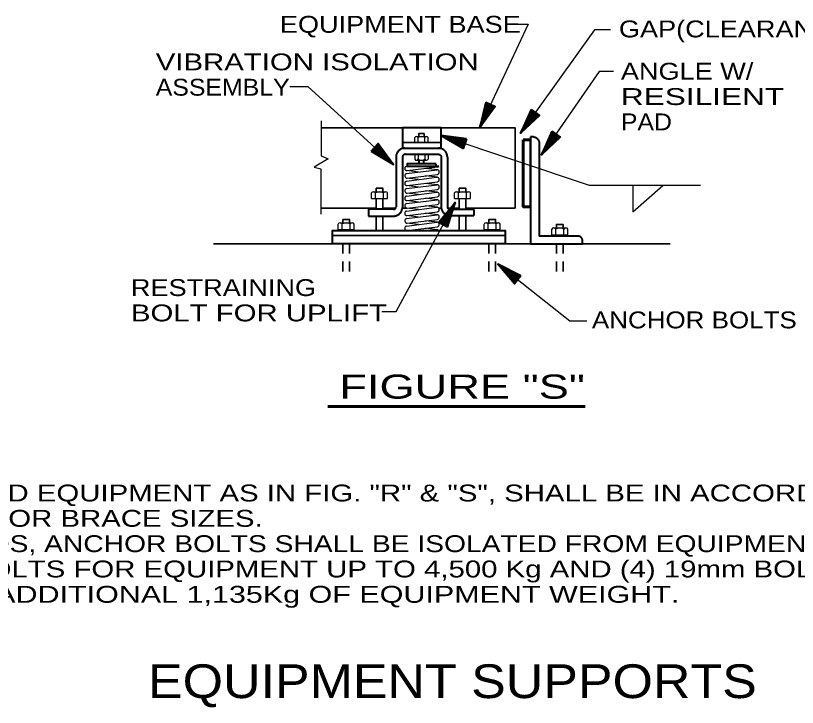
# Model space of a CAD drawing. Extents: x 55 to 190, y 198 to 264.
# Drawn here: x 114.38 to 126.14, y 231.1 to 241.51 of the extents above; entities that cross this region are included whole.
import ezdxf
from ezdxf.enums import TextEntityAlignment as Align

# ---------------------------------------------------------------- set-up
doc = ezdxf.new("R2010")
doc.units = 0
doc.header["$LTSCALE"] = 0.1
doc.linetypes.add('SHORT_DASHED', pattern=[2.7, 1.5, -1.2])
doc.layers.add('2', color=7, linetype='Continuous', lineweight=40)

msp = doc.modelspace()

# ---------------------------------------------------------------- linework, layer by layer
at = {"layer": '2'}
for p, q in [((121.3624, 239.8256), (121.473, 240.196)), ((121.3624, 239.8256), (121.4926, 240.1876)), ((121.3624, 239.8256), (121.5079, 240.1796)), ((121.5241, 240.1725), (121.3624, 239.8256)), ((121.3624, 239.8256), (121.5413, 240.164)), ((121.3624, 239.8256), (121.5752, 240.1481)), ((121.9762, 239.7399), (122.1527, 240.0838)), ((121.9762, 239.7399), (122.1705, 240.0719)), ((121.9762, 239.7399), (122.184, 240.0616)), ((122.1985, 240.0513), (121.9762, 239.7399)), ((121.9762, 239.7399), (122.2139, 240.0399)), ((121.9762, 239.7399), (122.2443, 240.0182)), ((121.1399, 239.5832), (120.7766, 239.7039)), ((120.7766, 239.7039), (121.151, 239.6161)), ((120.7766, 239.7039), (121.1217, 239.5298)), ((120.7766, 239.7039), (121.1336, 239.565)), ((120.7766, 239.7039), (121.1452, 239.6002)), ((120.7766, 239.7039), (121.1574, 239.6367)), ((122.1744, 239.6856), (122.1279, 239.6856)), ((122.2903, 239.4115), (122.4615, 239.7581)), ((122.2903, 239.4115), (122.4795, 239.7465)), ((122.2903, 239.4115), (122.493, 239.7362)), ((122.5078, 239.7264), (122.2903, 239.4115)), ((122.2903, 239.4115), (122.5234, 239.7153)), ((122.2903, 239.4115), (122.5541, 239.6939)), ((120.0633, 239.2687), (119.8183, 239.5676)), ((122.1279, 238.6326), (122.1279, 239.6377)), ((122.2591, 239.5944), (122.2591, 238.1915)), ((120.0633, 239.2687), (119.7424, 239.4843)), ((120.0633, 239.2687), (119.7564, 239.5004)), ((120.0633, 239.2687), (119.7683, 239.5126)), ((119.78, 239.5261), (120.0633, 239.2687)), ((120.0633, 239.2687), (119.7932, 239.5399)), ((120.1035, 239.3792), (120.1035, 238.63)), ((120.2014, 239.3816), (120.2014, 238.6228)), ((120.2438, 239.4216), (120.742, 239.4216)), ((120.4464, 239.3324), (120.4464, 239.2755)), ((120.5237, 239.2755), (120.5237, 239.3324)), ((120.783, 239.3792), (120.783, 238.6305)), ((120.8769, 239.3792), (120.8769, 238.6305)), ((120.2623, 239.2443), (120.7478, 239.2443)), ((120.7044, 239.2761), (120.7044, 239.2443)), ((120.9912, 238.6977), (120.7605, 238.3876)), ((120.9912, 238.6977), (120.7933, 238.3699)), ((120.8102, 238.3606), (120.9912, 238.6977)), ((120.9912, 238.6977), (120.8259, 238.3524)), ((120.9912, 238.6977), (120.8407, 238.3439)), ((120.9912, 238.6977), (120.8597, 238.3342)), ((120.0625, 238.5956), (119.6889, 238.5956)), ((119.6889, 238.5956), (119.6889, 238.4929)), ((120.914, 238.5937), (121.2727, 238.5937)), ((121.2727, 238.5929), (121.2727, 238.5014)), ((119.6889, 238.4916), (120.057, 238.4916)), ((120.9166, 238.5001), (121.2727, 238.5001)), ((122.8417, 238.1915), (122.2591, 238.1915)), ((121.9342, 237.533), (121.6336, 237.7698)), ((121.6336, 237.7698), (121.9561, 237.5603)), ((121.6336, 237.7698), (121.899, 237.4888)), ((121.6336, 237.7698), (121.9223, 237.5182)), ((121.6336, 237.7698), (121.945, 237.5473)), ((121.6336, 237.7698), (121.9689, 237.5774))]:
    msp.add_line(p, q, dxfattribs=at)
at = {"layer": '2', "lineweight": 25}
for p, q in [((120.4107, 239.6899), (120.561, 239.6899)), ((120.3856, 239.605), (120.3856, 239.6748)), ((120.3856, 239.605), (120.5861, 239.605)), ((120.4353, 239.605), (120.4353, 239.6748)), ((120.5361, 239.605), (120.5361, 239.6748)), ((120.5861, 239.605), (120.5861, 239.6743)), ((120.3856, 239.4166), (120.5861, 239.4166)), ((120.3856, 239.4166), (120.3856, 239.3467)), ((120.4107, 239.3316), (120.561, 239.3316)), ((120.4353, 239.4166), (120.4353, 239.3467)), ((120.5361, 239.4166), (120.5361, 239.3467)), ((120.5861, 239.4166), (120.5861, 239.3472)), ((120.2692, 239.1755), (120.7269, 239.2319)), ((120.4406, 239.1536), (120.2623, 239.1753)), ((120.2626, 239.1316), (120.7205, 239.188)), ((120.2694, 239.0628), (120.7274, 239.1192)), ((120.7272, 239.188), (120.5486, 239.2099)), ((120.7277, 239.0752), (120.5488, 239.0972)), ((120.2623, 239.0189), (120.72, 239.0752)), ((120.4409, 239.0409), (120.2628, 239.0626)), ((120.2692, 238.9501), (120.7269, 239.0065)), ((120.7272, 238.9625), (120.5486, 238.9845)), ((120.4406, 238.9281), (120.2623, 238.9498)), ((120.2626, 238.9062), (120.7205, 238.9625)), ((120.2694, 238.8374), (120.7274, 238.8938)), ((120.7277, 238.8498), (120.5488, 238.8718)), ((123.6683, 238.957), (123.6683, 238.5569)), ((123.6683, 238.5569), (124.1202, 238.9538)), ((119.7342, 238.7556), (119.7342, 238.8403)), ((119.7342, 238.7556), (119.9768, 238.7556)), ((119.7646, 238.8588), (119.9466, 238.8588)), ((119.7942, 238.7556), (119.7942, 238.8403)), ((119.9162, 238.7556), (119.9162, 238.8403)), ((119.9768, 238.7556), (119.9768, 238.8398)), ((120.2623, 238.7935), (120.72, 238.8498)), ((120.4409, 238.8154), (120.2628, 238.8371)), ((120.2692, 238.7247), (120.7269, 238.781)), ((120.7272, 238.7371), (120.5486, 238.7591)), ((120.9838, 238.7556), (120.9838, 238.8403)), ((120.9838, 238.7556), (121.2264, 238.7556)), ((121.0142, 238.8588), (121.1963, 238.8588)), ((121.0439, 238.7556), (121.0439, 238.8403)), ((121.1658, 238.7556), (121.1658, 238.8403)), ((121.2264, 238.7556), (121.2264, 238.8398)), ((120.4406, 238.7027), (120.2623, 238.7244)), ((120.2626, 238.6808), (120.7205, 238.7371)), ((120.2694, 238.612), (120.7274, 238.6683)), ((120.7277, 238.6244), (120.5488, 238.6464)), ((120.2623, 238.568), (120.72, 238.6244)), ((120.2626, 238.4553), (120.7205, 238.5114)), ((120.4409, 238.59), (120.2628, 238.6117)), ((120.2692, 238.4993), (120.7269, 238.5553)), ((120.7272, 238.5114), (120.5486, 238.5334)), ((119.263, 238.3913), (119.445, 238.3913)), ((120.4406, 238.477), (120.2623, 238.499)), ((120.2623, 238.3426), (120.72, 238.3987)), ((120.2694, 238.3865), (120.7274, 238.4426)), ((120.7277, 238.3987), (120.5488, 238.4207)), ((121.4606, 238.3913), (121.6426, 238.3913)), ((119.2325, 238.2881), (119.2325, 238.3728)), ((119.2325, 238.2881), (119.4752, 238.2881)), ((119.2926, 238.2881), (119.2926, 238.3728)), ((119.4146, 238.2881), (119.4146, 238.3728)), ((119.4752, 238.2881), (119.4752, 238.3723)), ((120.4409, 238.3643), (120.2628, 238.3863)), ((120.2692, 238.2738), (120.7269, 238.3299)), ((120.7203, 238.2871), (120.5486, 238.308)), ((120.6123, 238.2738), (120.7203, 238.2871)), ((121.4302, 238.2881), (121.4302, 238.3728)), ((121.4302, 238.2881), (121.6728, 238.2881)), ((121.4902, 238.2881), (121.4902, 238.3728)), ((121.6122, 238.2881), (121.6122, 238.3728)), ((121.6728, 238.2881), (121.6728, 238.3723)), ((122.4459, 238.2117), (122.4459, 238.2963)), ((122.4763, 238.3148), (122.6583, 238.3148)), ((122.506, 238.2117), (122.506, 238.2963)), ((122.6279, 238.2117), (122.6279, 238.2963)), ((122.6885, 238.2117), (122.6885, 238.2958)), ((122.4459, 238.2117), (122.6885, 238.2117))]:
    msp.add_line(p, q, dxfattribs=at)
at = {"layer": '2', "lineweight": 35}
for p, q in [((120.202, 239.5981), (120.7835, 239.5981)), ((119.8059, 238.7556), (119.8059, 238.5948)), ((119.9056, 238.7556), (119.9056, 238.5966)), ((121.0555, 238.7556), (121.0555, 238.5948)), ((121.1552, 238.7556), (121.1552, 238.5937)), ((119.8059, 238.6109), (118.987, 238.6117)), ((120.0975, 238.6104), (119.9056, 238.6106)), ((120.2647, 238.6104), (120.1988, 238.6104)), ((120.7848, 238.6099), (120.7488, 238.6099)), ((121.0555, 238.6096), (120.883, 238.6099)), ((121.8953, 238.6088), (121.1552, 238.6096)), ((119.8059, 238.4916), (119.8059, 238.2738)), ((119.9056, 238.4916), (119.9056, 238.2738)), ((121.0555, 238.5001), (121.0555, 238.2738)), ((121.1552, 238.5001), (121.1552, 238.2738)), ((119.1479, 238.1989), (121.7471, 238.1989)), ((117.3582, 238.0762), (124.2287, 238.0762))]:
    msp.add_line(p, q, dxfattribs=at)
at = {"layer": '2', "lineweight": 60}
for p, q in [((122.1279, 239.6377), (122.0167, 239.6377)), ((119.0772, 235.6246), (122.9497, 235.6246))]:
    msp.add_line(p, q, dxfattribs=at)
at = {"layer": '2', "linetype": 'SHORT_DASHED', "lineweight": 35}
for p, q in [((119.3042, 238.0765), (119.3042, 237.569)), ((119.404, 238.0765), (119.404, 237.569)), ((121.5019, 238.0765), (121.5019, 237.569)), ((121.6016, 238.0765), (121.6016, 237.569)), ((122.5176, 238.0765), (122.5176, 237.569)), ((122.6173, 238.0765), (122.6173, 237.569))]:
    msp.add_line(p, q, dxfattribs=at)
at = {"layer": '2', "lineweight": 25}
for points in [[(121.8479, 241.3816), (122.0906, 241.3816), (121.3624, 239.8256)], [(123.3325, 241.2962), (123.0899, 241.2962), (121.9762, 239.7399)], [(123.3754, 240.6678), (123.1613, 240.6678), (122.2903, 239.4115)], [(118.507, 240.4394), (118.7782, 240.4394), (120.0633, 239.2687)], [(118.978, 239.9251), (118.978, 239.397), (119.0849, 239.3541), (118.8708, 239.2255), (118.9708, 239.2041), (118.9708, 238.5188)], [(120.7766, 239.7039), (123.0108, 238.9578), (124.6856, 238.9578)], [(119.8919, 237.0559), (120.1062, 237.0559), (120.9912, 238.6977)], [(122.9756, 236.9131), (122.7187, 236.9131), (121.6336, 237.7698)]]:
    msp.add_lwpolyline(points, dxfattribs=at)
at = {"layer": '2'}
for points in [[(121.4556, 240.2042), (121.5939, 240.1391), (121.3624, 239.8256)], [(121.4556, 240.2042), (121.3624, 239.8256), (121.5587, 240.1563)], [(122.1369, 240.0952), (122.2612, 240.006), (121.9762, 239.7399)], [(122.1369, 240.0952), (121.9762, 239.7399), (122.2295, 240.0293)], [(121.1635, 239.6552), (121.1148, 239.51), (120.7766, 239.7039)], [(121.1635, 239.6552), (120.7766, 239.7039), (121.1277, 239.547)], [(122.1279, 239.6856), (122.1279, 238.0762), (122.9108, 238.0762), (122.9108, 238.1188)], [(122.1744, 239.6856), (122.1792, 239.6843), (122.1842, 239.683), (122.189, 239.6814), (122.1937, 239.6796), (122.1982, 239.6774), (122.2027, 239.6751), (122.2072, 239.6727), (122.2115, 239.67), (122.2157, 239.6671), (122.2197, 239.664), (122.2236, 239.6608), (122.2274, 239.6571), (122.2308, 239.6536), (122.2342, 239.6499), (122.2374, 239.646), (122.2403, 239.6417), (122.2432, 239.6375), (122.2459, 239.6333), (122.2483, 239.6287), (122.2504, 239.6243), (122.2525, 239.6195), (122.2541, 239.6147), (122.2557, 239.61), (122.257, 239.6052), (122.2594, 239.5944)], [(122.4456, 239.7693), (122.571, 239.6817), (122.2903, 239.4115)], [(122.4456, 239.7693), (122.2903, 239.4115), (122.5393, 239.7047)], [(119.7292, 239.4697), (119.8326, 239.5827), (120.0633, 239.2687)], [(119.7292, 239.4697), (120.0633, 239.2687), (119.8059, 239.5541)], [(120.2422, 239.5155), (120.2316, 239.5153), (120.2208, 239.5139), (120.2104, 239.5118), (120.2001, 239.5089), (120.1877, 239.5052), (120.1779, 239.5007), (120.1686, 239.4954), (120.1596, 239.4896), (120.1512, 239.483), (120.1435, 239.4756), (120.1361, 239.4679), (120.1295, 239.4594), (120.1236, 239.4504), (120.1184, 239.4412), (120.1138, 239.4314), (120.1102, 239.4213), (120.1072, 239.411), (120.1051, 239.4007), (120.1038, 239.3901), (120.1035, 239.3792)], [(120.8769, 239.3792), (120.8764, 239.3898), (120.8751, 239.4004), (120.8732, 239.4107), (120.8703, 239.4211), (120.8666, 239.4311), (120.8621, 239.4406), (120.8571, 239.4499), (120.851, 239.4586), (120.8444, 239.4671), (120.8372, 239.4748), (120.8296, 239.4819), (120.8211, 239.4885), (120.8124, 239.4944), (120.8031, 239.4996), (120.7936, 239.5041), (120.7835, 239.5078), (120.7732, 239.5105), (120.7629, 239.5126), (120.7523, 239.5139), (120.7417, 239.5145)], [(120.2438, 239.4216), (120.2403, 239.4213), (120.2372, 239.4211), (120.2337, 239.4205), (120.2305, 239.4195), (120.2274, 239.4184), (120.2244, 239.4168), (120.2215, 239.4152), (120.2189, 239.4134), (120.2163, 239.4115), (120.2136, 239.4092), (120.2115, 239.4068), (120.2094, 239.4041), (120.2075, 239.4012), (120.2059, 239.3983), (120.2046, 239.3954), (120.2033, 239.3922), (120.2025, 239.389), (120.202, 239.3859), (120.2014, 239.3824), (120.2014, 239.3816)], [(120.742, 239.4216), (120.7452, 239.4216), (120.7483, 239.4211), (120.7515, 239.4205), (120.7547, 239.4197), (120.7578, 239.4187), (120.7608, 239.4173), (120.7637, 239.4158), (120.7663, 239.4139), (120.769, 239.4121), (120.7713, 239.4097), (120.7735, 239.4073), (120.7756, 239.4049), (120.7774, 239.4023), (120.779, 239.3994), (120.7803, 239.3965), (120.7817, 239.3933), (120.7825, 239.3901), (120.783, 239.3869), (120.7835, 239.3838), (120.7835, 239.3806)], [(120.7044, 239.2761), (120.2718, 239.2761), (120.2718, 239.2443)], [(120.0625, 238.5956), (120.0657, 238.5953), (120.0686, 238.5953), (120.0718, 238.5953), (120.0747, 238.5958), (120.0776, 238.5966), (120.0805, 238.5977), (120.0832, 238.5987), (120.0861, 238.6003), (120.0885, 238.6019), (120.0908, 238.6038), (120.0932, 238.6059), (120.0951, 238.608), (120.0969, 238.6104), (120.0988, 238.613), (120.1001, 238.6157), (120.1012, 238.6186), (120.1022, 238.6215), (120.103, 238.6244), (120.1033, 238.6273), (120.1033, 238.6284)], [(120.8769, 238.3249), (120.7422, 238.3977), (120.9912, 238.6977)], [(120.8769, 238.3249), (120.9912, 238.6977), (120.7766, 238.3786)], [(120.783, 238.6305), (120.7835, 238.6199), (120.7848, 238.6099), (120.7869, 238.5995), (120.7899, 238.5895), (120.7936, 238.58), (120.7978, 238.5704), (120.8031, 238.5614), (120.8089, 238.553), (120.8155, 238.5448), (120.8227, 238.5374), (120.8304, 238.5302), (120.8386, 238.5241), (120.8473, 238.5183), (120.8563, 238.5135), (120.8658, 238.5093), (120.8756, 238.5059), (120.8856, 238.5032), (120.896, 238.5014), (120.9063, 238.5003), (120.9166, 238.5001)], [(120.8769, 238.6305), (120.8769, 238.6273), (120.8774, 238.6244), (120.8782, 238.6215), (120.879, 238.6186), (120.8801, 238.6157), (120.8814, 238.613), (120.883, 238.6104), (120.8849, 238.608), (120.887, 238.6056), (120.8891, 238.6035), (120.8915, 238.6017), (120.8939, 238.5998), (120.8965, 238.5982), (120.8991, 238.5969), (120.9021, 238.5958), (120.905, 238.595), (120.9079, 238.5942), (120.9108, 238.594), (120.914, 238.5937), (120.9169, 238.5937)], [(120.057, 238.4916), (120.0684, 238.4918), (120.0795, 238.4926), (120.0903, 238.4945), (120.1012, 238.4971), (120.1117, 238.5008), (120.122, 238.5051), (120.1321, 238.5104), (120.1414, 238.5162), (120.1504, 238.5231), (120.1588, 238.5305), (120.1665, 238.5384), (120.1737, 238.5471), (120.1789, 238.5564), (120.1845, 238.5659), (120.1895, 238.576), (120.1935, 238.5866), (120.1967, 238.5972), (120.1988, 238.6083), (120.2004, 238.6191), (120.2004, 238.6215)], [(122.9102, 238.1135), (122.9105, 238.1183), (122.9105, 238.1233), (122.91, 238.128), (122.9092, 238.1331), (122.9081, 238.1378), (122.9065, 238.1426), (122.9049, 238.1471), (122.9028, 238.1516), (122.9005, 238.1561), (122.8978, 238.1601), (122.8949, 238.164), (122.8917, 238.168), (122.8883, 238.1714), (122.8846, 238.1746), (122.8806, 238.1778), (122.8766, 238.1804), (122.8721, 238.1831), (122.8679, 238.1852), (122.8631, 238.187), (122.8586, 238.1886), (122.8539, 238.1899), (122.8489, 238.1907), (122.8441, 238.1915), (122.8417, 238.1915)], [(121.981, 237.5928), (121.886, 237.4727), (121.6336, 237.7698)], [(121.981, 237.5928), (121.6336, 237.7698), (121.9106, 237.5031)]]:
    msp.add_lwpolyline(points, dxfattribs=at)
at = {"layer": '2', "lineweight": 35}
for points in [[(121.8953, 238.6088), (121.8953, 239.8216), (118.987, 239.8216)], [(120.5271, 239.6904), (120.5271, 239.7325), (120.4448, 239.7325), (120.4448, 239.6904)], [(119.9056, 238.8594), (119.9056, 238.9101), (119.8059, 238.9101), (119.8059, 238.8594)], [(121.1552, 238.8594), (121.1552, 238.9101), (121.0555, 238.9101), (121.0555, 238.8594)], [(119.404, 238.3918), (119.404, 238.4426), (119.3042, 238.4426), (119.3042, 238.3918)], [(121.6016, 238.3918), (121.6016, 238.4426), (121.5019, 238.4426), (121.5019, 238.3918)], [(122.6173, 238.3154), (122.6173, 238.3662), (122.5176, 238.3662), (122.5176, 238.3154)]]:
    msp.add_lwpolyline(points, dxfattribs=at)
at = {"layer": '2'}
for points in [[(120.2017, 239.8216), (120.2017, 239.5155), (120.7835, 239.5155), (120.7835, 239.8216)], [(119.1479, 238.0765), (119.1479, 238.2738), (121.7471, 238.2738), (121.7471, 238.0765)]]:
    msp.add_lwpolyline(points, close=True, dxfattribs=at)
at = {"layer": '2', "lineweight": 60}
msp.add_lwpolyline([(122.0167, 239.6377), (122.0167, 238.6326), (122.1279, 238.6326)], dxfattribs=at)
at = {"layer": '2', "lineweight": 25}
for centre, radius, start, end in [((120.4105, 239.6619), 0.028, 27.8877, 152.03419), ((120.4857, 239.5973), 0.0926, 57.00616, 122.94297), ((120.5609, 239.6617), 0.028, 26.78269, 151.8391), ((120.4105, 239.3596), 0.028, 207.96581, 332.1123), ((120.4857, 239.4242), 0.0926, 237.05703, 302.99384), ((120.5609, 239.3598), 0.028, 208.1609, 333.21731), ((119.7644, 238.8247), 0.0339, 27.8877, 152.03419), ((119.8554, 238.7465), 0.1121, 57.00616, 122.94297), ((119.9464, 238.8244), 0.0339, 26.78269, 151.8391), ((121.014, 238.8247), 0.0339, 27.8877, 152.03419), ((121.105, 238.7465), 0.1121, 57.00616, 122.94297), ((121.196, 238.8244), 0.0339, 26.78269, 151.8391), ((119.2628, 238.3572), 0.0339, 27.8877, 152.03419), ((119.3537, 238.279), 0.1121, 57.00616, 122.94297), ((119.4447, 238.3569), 0.0339, 26.78269, 151.8391), ((121.4604, 238.3572), 0.0339, 27.8877, 152.03419), ((121.5514, 238.279), 0.1121, 57.00616, 122.94297), ((121.6424, 238.3569), 0.0339, 26.78269, 151.8391), ((122.4761, 238.2807), 0.0339, 27.8877, 152.03419), ((122.5671, 238.2025), 0.1121, 57.00616, 122.94297), ((122.6581, 238.2804), 0.0339, 26.78269, 151.8391)]:
    msp.add_arc(centre, radius, start, end, dxfattribs=at)
for centre, major_axis, start_param, end_param in [((120.2657, 239.2098), (0, -0.0346), 3.2517222, 6.3933148), ((120.2661, 239.0971), (0, -0.0346), 3.2517222, 6.3933148), ((120.7239, 239.1534), (0, 0.0346), 3.2517222, 6.3933148), ((120.2657, 238.9844), (0, -0.0346), 3.2517222, 6.3933148), ((120.7235, 239.0407), (0, 0.0346), 3.2517222, 6.3933148), ((120.2661, 238.8717), (0, -0.0346), 3.2517222, 6.3933148), ((120.7239, 238.9279), (0, 0.0346), 3.2517222, 6.3933148), ((120.2657, 238.7589), (0, -0.0346), 3.2517222, 6.3933148), ((120.7235, 238.8152), (0, 0.0346), 3.2517222, 6.3933148), ((120.2661, 238.6462), (0, -0.0346), 3.2517222, 6.3933148), ((120.7235, 238.5898), (0, 0.0346), 3.2517222, 6.3933148), ((120.7239, 238.7025), (0, 0.0346), 3.2517222, 6.3933148), ((120.2657, 238.5335), (0, -0.0346), 3.2517222, 6.3933148), ((120.7239, 238.4771), (0, 0.0346), 3.2517222, 6.3933148), ((120.2661, 238.4208), (0, -0.0346), 3.2517222, 6.3933148), ((120.7235, 238.3644), (0, 0.0346), 3.2517222, 6.3933148), ((120.2657, 238.3081), (0, -0.0346), 3.2517222, 6.3933148), ((120.7203, 238.2525), (0, 0.0346), 5.3617333, 6.3941597)]:
    msp.add_ellipse(centre, major_axis=major_axis, ratio=0.9, start_param=start_param, end_param=end_param, dxfattribs=at)
at = {"layer": '2'}
msp.add_ellipse((120.7235, 239.2661), major_axis=(0, 0.0346), ratio=0.9, start_param=3.2517222, end_param=4.0304893, dxfattribs=at)

# ---------------------------------------------------------------- texts
for s, width, p in [('EQUIPMENT BASE', 1.2, (118.3565, 241.2499)), ('GAP(CLEARANCE)', 1.2, (123.4571, 241.1803)), ('VIBRATION ISOLATION', 1.3, (116.4891, 240.6845)), ('ANGLE W/', 1.2, (123.4865, 240.544)), ('ASSEMBLY', 1.1, (116.4891, 240.3035)), ('RESILIENT ', 1.4, (123.4865, 240.1629)), ('PAD', 1.1, (123.4865, 239.782)), ('RESTRAINING', 1.2, (116.1155, 237.2888)), ('BOLT FOR UPLIFT', 1.3, (116.1155, 236.9078)), ('ANCHOR BOLTS', 1.15, (123.0507, 236.8027)), ('1. CLEARANCES AT SIDES FOR SPRING MOUNTED EQUIPMENT AS IN FIG. "R" & "S", SHALL BE IN ACCORDANCE WITH MFR\'S. RECOMMENDATIONS.', 1.3, (103.733, 234.1984)), ('2. SEE MAXIMUM BRACING LENGTHS, TABLE 1, FOR BRACE SIZES.', 1.3, (103.7692, 233.8174)), ('3. IF EQUIPMENT IS MOUNTED ON NEOPRENE PADS, ANCHOR BOLTS SHALL BE ISOLATED FROM EQUIPMENT BY A NEOPRENE SLEEVE AND WASHER.', 1.25, (103.7692, 233.4363)), ('4. PROVIDE A MINIMUM OF (4) 13mm ANCHOR BOLTS FOR EQUIPMENT UP TO 4,500 Kg AND (4) 19mm BOLTS FOR EQUIPMENT WEIGHT OF 4,500Kg OR GREATER.', 1.3, (103.7692, 233.0554)), ('   ADD (1) ADDITIONAL 19mm BOLT FOR EACH ADDITIONAL 1,135Kg OF EQUIPMENT WEIGHT.', 1.35, (103.8058, 232.6744))]:
    msp.add_text(s, height=0.254, dxfattribs=dict(at, width=width)).set_placement(p)
for s, height, width, p in [('FIGURE "S"', 0.3633, 1.4, (121.098, 235.7447)), ('EQUIPMENT SUPPORTS', 0.508, 1.15, (120.9519, 231.2401))]:
    msp.add_text(s, height=height, dxfattribs=dict(at, width=width)).set_placement(p, align=Align.CENTER)

doc.saveas('drawing.dxf')
